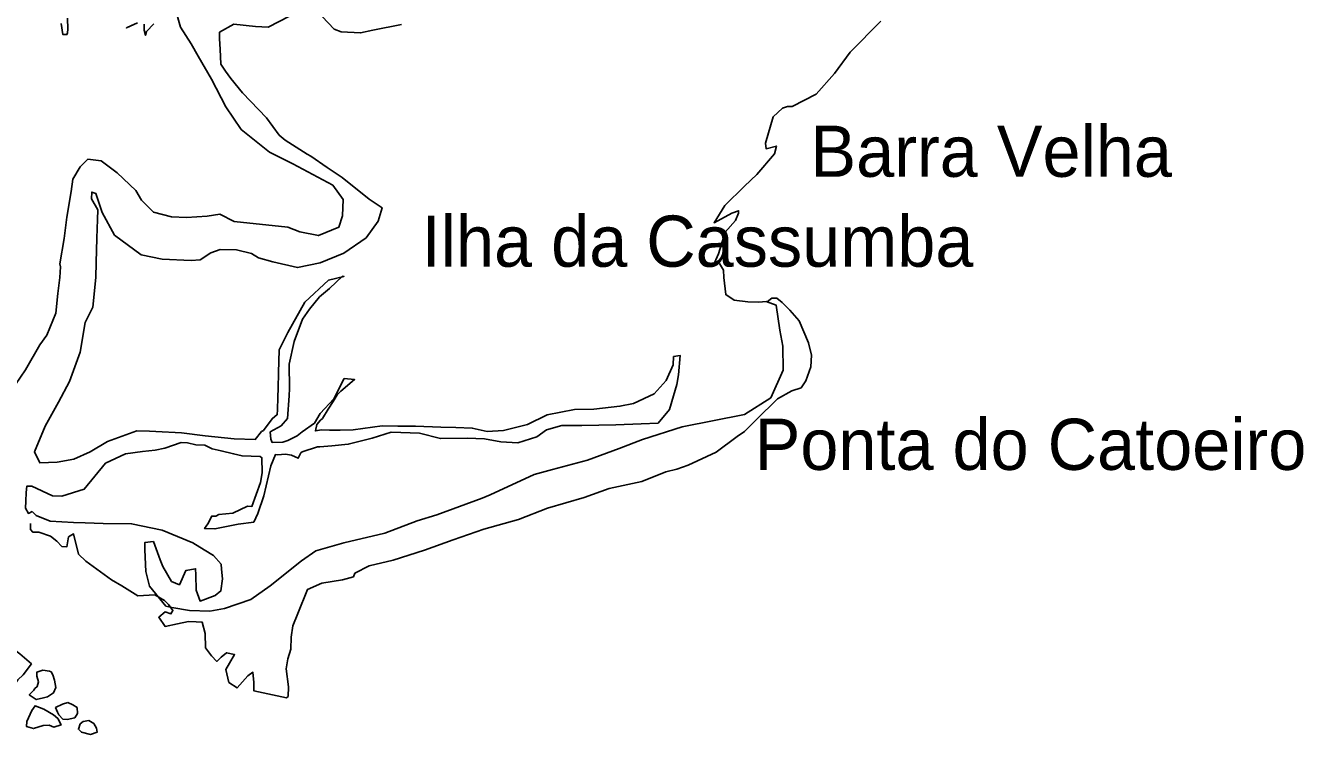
# Model space of a CAD drawing. Extents: x 662444 to 1640468, y 7452018 to 9606170.
# Drawn here: x 1098601 to 1114914, y 8010563 to 8019615 of the extents above; entities that cross this region are included whole.
import ezdxf

# ---------------------------------------------------------------- set-up
doc = ezdxf.new("R2010")
doc.units = 0
doc.layers.add('Level 1', color=7, linetype='Continuous')
doc.layers.add('Level 3', color=7, linetype='Continuous')

msp = doc.modelspace()

# ---------------------------------------------------------------- linework, layer by layer
at = {"layer": 'Level 1'}
for points in [[(1098473, 8015030), (1098602, 8015219), (1098782, 8015539), (1098871, 8015659), (1098988, 8015942), (1099011, 8016195), (1099040, 8016396), (1099045, 8016535), (1099038, 8016574), (1099095, 8016897), (1099126, 8017166), (1099183, 8017497), (1099203, 8017651), (1099300, 8017810), (1099397, 8017907), (1099566, 8017886), (1099770, 8017733), (1100010, 8017509), (1100083, 8017383), (1100233, 8017231), (1100463, 8017170), (1100655, 8017164), (1100919, 8017179), (1101083, 8017204), (1101265, 8017113), (1101950, 8017038), (1102102, 8016979), (1102340, 8016933), (1102599, 8017040), (1102649, 8017186), (1102656, 8017394), (1102523, 8017576), (1102014, 8017848), (1101717, 8017996), (1101355, 8018286), (1101156, 8018577), (1100973, 8018932), (1100805, 8019223), (1100717, 8019380), (1100577, 8019593), (1100508, 8019850)], [(1098686, 8013408), (1098737, 8013360), (1098913, 8013286), (1099214, 8013268), (1099360, 8013263), (1099592, 8013256), (1099955, 8013252), (1100346, 8013170), (1100735, 8013011), (1100879, 8012921), (1101000, 8012847), (1101097, 8012737), (1101103, 8012674), (1101114, 8012550), (1101094, 8012396), (1101023, 8012337), (1100828, 8012266), (1100778, 8012406), (1100776, 8012600), (1100771, 8012678), (1100647, 8012658), (1100564, 8012475), (1100465, 8012517), (1100355, 8012706), (1100319, 8012793), (1100234, 8013026), (1100125, 8013015), (1100122, 8012922), (1100137, 8012644), (1100184, 8012456), (1100393, 8012202), (1100470, 8012184), (1100692, 8012146), (1100955, 8012138), (1101141, 8012170), (1101477, 8012284), (1101722, 8012462), (1102125, 8012781), (1102307, 8012906), (1102666, 8013011), (1103187, 8013134), (1103602, 8013290), (1103851, 8013367), (1104429, 8013581), (1104532, 8013624), (1105095, 8013884), (1105329, 8013947), (1105774, 8014063), (1106180, 8014213), (1106477, 8014328), (1106984, 8014489), (1107777, 8014649), (1108116, 8014862), (1108274, 8015213), (1108268, 8015522), (1108228, 8015725), (1108185, 8016043), (1108054, 8016093), (1107961, 8016081), (1107823, 8016085), (1107646, 8016106), (1107539, 8016180), (1107515, 8016396), (1107510, 8016490), (1107459, 8016576), (1107397, 8016585), (1107448, 8016701), (1107534, 8016976), (1107662, 8017127), (1107703, 8017218), (1107704, 8017249), (1107618, 8017220), (1107391, 8017096), (1107528, 8017316), (1107777, 8017563), (1107936, 8017713), (1108160, 8017976), (1108186, 8018076), (1108054, 8018041), (1108048, 8018111), (1108144, 8018448), (1108263, 8018560), (1108326, 8018582), (1108387, 8018580), (1108694, 8018739), (1108926, 8019002), (1109129, 8019274), (1109519, 8019671)], [(1099135, 8019708), (1099140, 8019569), (1099138, 8019523), (1099129, 8019499), (1099076, 8019502), (1099057, 8019642)], [(1101972, 8019734), (1101697, 8019596), (1101536, 8019602), (1101259, 8019634), (1101078, 8019532)], [(1103398, 8019628), (1103033, 8019554), (1102877, 8019520), (1102630, 8019535), (1102539, 8019569), (1102389, 8019730)], [(1101078, 8019532), (1101075, 8019446), (1101086, 8019314), (1101095, 8019121), (1101154, 8019034), (1101222, 8018939), (1101370, 8018757), (1101677, 8018438), (1101840, 8018216), (1101915, 8018152), (1102195, 8017973), (1102241, 8017948), (1102453, 8017803), (1102642, 8017673), (1102988, 8017399), (1103155, 8017286), (1103103, 8017117), (1102950, 8016905), (1102666, 8016706), (1102361, 8016584), (1102072, 8016524), (1101758, 8016596), (1101575, 8016648), (1101484, 8016705), (1101292, 8016750), (1101084, 8016756), (1100966, 8016713), (1100832, 8016625), (1100716, 8016613), (1100345, 8016633), (1100077, 8016688), (1099737, 8016938), (1099577, 8017229), (1099499, 8017471), (1099445, 8017489), (1099442, 8017403), (1099523, 8017262), (1099520, 8017138), (1099512, 8016898), (1099503, 8016590), (1099496, 8016396), (1099461, 8016019), (1099363, 8015821), (1099297, 8015445), (1099162, 8015070), (1099022, 8014804), (1098851, 8014500), (1098716, 8014172), (1098782, 8014031), (1099006, 8014040), (1099216, 8014079), (1099427, 8014173), (1099648, 8014305), (1100022, 8014440), (1100185, 8014435), (1100262, 8014433), (1100593, 8014414), (1100893, 8014374), (1101263, 8014339), (1101533, 8014330), (1101613, 8014429), (1101637, 8014443), (1101749, 8014593), (1101813, 8014646), (1101816, 8014708), (1101821, 8014870), (1101824, 8014986), (1101830, 8015179), (1101839, 8015472), (1101947, 8015693), (1102167, 8016081), (1102470, 8016364), (1102664, 8016412), (1102649, 8016413), (1102482, 8016256), (1102355, 8016152), (1102227, 8015993), (1102137, 8015865), (1102028, 8015582), (1101964, 8015291), (1101971, 8014981), (1101968, 8014888), (1101943, 8014595), (1101863, 8014505), (1101722, 8014425), (1101734, 8014332), (1101748, 8014292), (1101887, 8014296), (1101950, 8014317), (1102068, 8014375), (1102131, 8014427), (1102289, 8014538), (1102363, 8014659), (1102538, 8014847), (1102670, 8015106), (1102801, 8015094), (1102626, 8014945), (1102579, 8014899), (1102529, 8014816), (1102464, 8014718), (1102392, 8014597)], [(1100030, 8019649), (1099889, 8019584), (1099960, 8019621)], [(1100239, 8019635), (1100143, 8019538), (1100133, 8019491), (1100113, 8019554), (1100115, 8019631)], [(1098663, 8013256), (1098663, 8013178), (1098693, 8013147), (1098771, 8013144), (1098921, 8013093), (1099001, 8013029), (1099063, 8012964), (1099127, 8012957), (1099147, 8013084), (1099214, 8013123), (1099277, 8012863), (1099371, 8012774), (1099696, 8012536), (1099829, 8012461), (1100033, 8012334), (1100252, 8012345), (1100376, 8012273), (1100427, 8012222), (1100481, 8012144), (1100457, 8012101), (1100381, 8012129), (1100302, 8012060), (1100381, 8011943), (1100542, 8011976), (1100679, 8012003), (1100778, 8012000), (1100855, 8011998), (1100892, 8011853), (1100896, 8011670), (1100973, 8011567), (1101042, 8011496), (1101097, 8011548), (1101168, 8011605), (1101269, 8011582), (1101204, 8011471), (1101159, 8011393), (1101196, 8011226), (1101302, 8011156), (1101438, 8011313), (1101503, 8011357), (1101514, 8011224), (1101513, 8011120), (1101934, 8011028), (1101953, 8011049), (1101957, 8011169), (1101928, 8011400), (1101948, 8011528), (1101986, 8011651), (1101991, 8011806), (1102014, 8011951), (1102075, 8012109), (1102199, 8012414), (1102384, 8012495), (1102648, 8012538), (1102786, 8012574), (1102806, 8012622), (1102986, 8012717), (1103292, 8012788), (1103694, 8012916), (1104059, 8013049), (1104452, 8013184), (1104892, 8013309), (1105265, 8013453), (1105731, 8013588), (1106050, 8013705), (1106467, 8013792), (1106774, 8013918), (1106916, 8013949), (1107059, 8014001), (1107417, 8014166), (1107684, 8014369), (1107777, 8014429), (1107928, 8014582), (1108202, 8014849), (1108384, 8014950), (1108502, 8014988), (1108562, 8015076), (1108626, 8015258), (1108633, 8015405), (1108597, 8015562), (1108476, 8015845), (1108357, 8015981), (1108260, 8016078), (1108193, 8016134), (1108127, 8016134), (1108069, 8016087), (1108054, 8016093)], [(1102392, 8014597), (1102367, 8014575), (1102319, 8014522), (1102302, 8014438), (1102379, 8014451), (1102480, 8014447), (1102618, 8014450), (1102781, 8014453), (1103153, 8014503), (1103353, 8014497), (1103578, 8014498), (1103902, 8014487), (1104095, 8014481), (1104303, 8014474), (1104495, 8014430), (1104704, 8014445), (1105007, 8014521), (1105258, 8014644), (1105608, 8014710), (1105856, 8014718), (1106189, 8014753), (1106360, 8014787), (1106626, 8014910), (1106778, 8015083), (1106869, 8015281), (1106873, 8015388), (1106958, 8015401), (1106936, 8015155), (1106916, 8015032), (1106873, 8014887), (1106821, 8014711), (1106676, 8014537), (1106460, 8014528), (1106135, 8014516), (1105702, 8014507), (1105448, 8014507), (1105252, 8014452), (1105126, 8014362), (1104884, 8014285), (1104668, 8014300), (1104461, 8014337), (1104237, 8014345), (1103897, 8014340), (1103629, 8014410), (1103390, 8014418), (1103267, 8014421), (1103025, 8014344), (1102721, 8014269), (1102512, 8014246), (1102357, 8014235), (1102326, 8014236), (1102131, 8014173), (1102115, 8014158), (1102082, 8014089), (1101998, 8014130), (1101944, 8014139), (1101913, 8014140), (1101821, 8014135), (1101790, 8014136), (1101731, 8013991), (1101642, 8013608), (1101566, 8013386), (1101515, 8013272), (1101313, 8013247), (1101019, 8013187), (1100887, 8013191), (1100928, 8013252), (1100977, 8013351), (1101000, 8013350), (1101031, 8013349), (1101070, 8013371), (1101249, 8013389), (1101436, 8013476), (1101491, 8013474), (1101601, 8013780), (1101620, 8013903), (1101618, 8014096), (1101595, 8014112), (1101365, 8014119), (1101257, 8014146), (1101096, 8014182), (1100981, 8014209), (1100890, 8014258), (1100774, 8014262), (1100667, 8014288), (1100589, 8014291), (1100379, 8014220), (1100254, 8014193), (1100092, 8014175), (1099875, 8014144), (1099623, 8014028), (1099350, 8013696), (1099062, 8013605), (1098946, 8013608), (1098680, 8013733), (1098618, 8013735), (1098608, 8013651), (1098605, 8013542), (1098602, 8013450), (1098638, 8013386), (1098686, 8013408)], [(1098440, 8011660), (1098527, 8011594), (1098675, 8011464), (1098570, 8011324), (1098504, 8011262), (1098365, 8011057), (1097980, 8010926), (1097633, 8010918), (1097352, 8010907), (1097056, 8010849), (1096805, 8010765), (1096405, 8011116)], [(1098987, 8011161), (1098959, 8011093), (1098879, 8011044), (1098832, 8011032), (1098737, 8011007), (1098647, 8011069), (1098707, 8011130), (1098718, 8011148), (1098747, 8011173), (1098764, 8011234), (1098746, 8011308), (1098745, 8011359), (1098822, 8011383), (1098906, 8011372), (1098927, 8011364), (1098951, 8011323), (1098969, 8011254), (1098987, 8011161)], [(1098956, 8010814), (1099011, 8010767), (1099054, 8010684), (1098961, 8010654), (1098903, 8010681), (1098826, 8010678), (1098703, 8010638), (1098611, 8010666), (1098618, 8010727), (1098682, 8010869), (1098722, 8010929), (1098833, 8010884), (1098956, 8010814)], [(1099140, 8010972), (1099205, 8010940), (1099258, 8010905), (1099265, 8010828), (1099228, 8010776), (1099133, 8010755), (1099077, 8010757), (1099027, 8010812), (1099008, 8010846), (1098984, 8010905), (1099072, 8010948), (1099140, 8010972)], [(1099471, 8010701), (1099507, 8010641), (1099513, 8010590), (1099431, 8010563), (1099316, 8010592), (1099275, 8010628), (1099297, 8010697), (1099337, 8010727), (1099408, 8010739), (1099471, 8010701)]]:
    msp.add_lwpolyline(points, dxfattribs=at)

# ---------------------------------------------------------------- texts
at = {"layer": 'Level 3'}
for s, height, p in [('Barra Velha', 653.39, (1108621, 8017683)), ('Ilha da Cassumba', 653.31, (1103659, 8016535)), ('Ponta do Catoeiro', 653.27, (1107909, 8013941))]:
    msp.add_text(s, height=height, dxfattribs=at).set_placement(p)

doc.saveas('drawing.dxf')
